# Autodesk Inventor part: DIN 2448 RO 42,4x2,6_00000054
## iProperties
Created: 2006-03
Part Number: DIN 2448 RO 42,4x2,6_00000054
Material: Default
Document SubType Name: Modeling
Designer: Carlo
Stock Number: DIN 2448 RO 42,4x2,6
Mass: 250.315 g
Surface Area: 1938.27 cm^2
Volume: 250.315 cm^3
Density: 1 g/cm^3
G_L: 800.000 mm
G_W: 42.400 mm
G_H: 42.400 mm
AFG_Item: 42.4 x 2.6
CSToolsMass: 0.3
CSToolsVolume: 250315.0
CSToolsArea: 1938.0
Author: Carlo
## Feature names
1. AFG_Detailed_DIN 2448 RO 42,4x2,6_00000054 [Extrusion]
2. AFG_Simplified_DIN 2448 RO 42,4x2,6_00000054 [Extrusion]
3. AFG_StartExtrusion_1 [Extrusion]
4. AFG_StartExtrusion_2 [Extrusion]
5. AFG_EndExtrusion_1 [Extrusion]
6. AFG_EndExtrusion_2 [Extrusion]
